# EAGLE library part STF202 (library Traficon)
USB Filter with ESD Protection
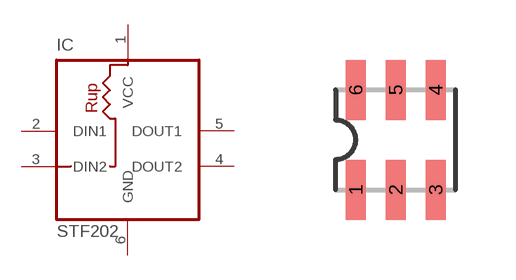
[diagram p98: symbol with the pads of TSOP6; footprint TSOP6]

Designator prefix IC

## STF202  [TSOP6]
1  VCC
2  DIN1
3  DIN2
4  DOUT2
5  DOUT1
6  GND

## Footprint TSOP6 (pad centres in mm)
smd 0.5 x 1.5: 1 -2,-1.5; 2 -1,-1.5; 3 0,-1.5; 4 0,1; 5 -1,1; 6 -2,1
